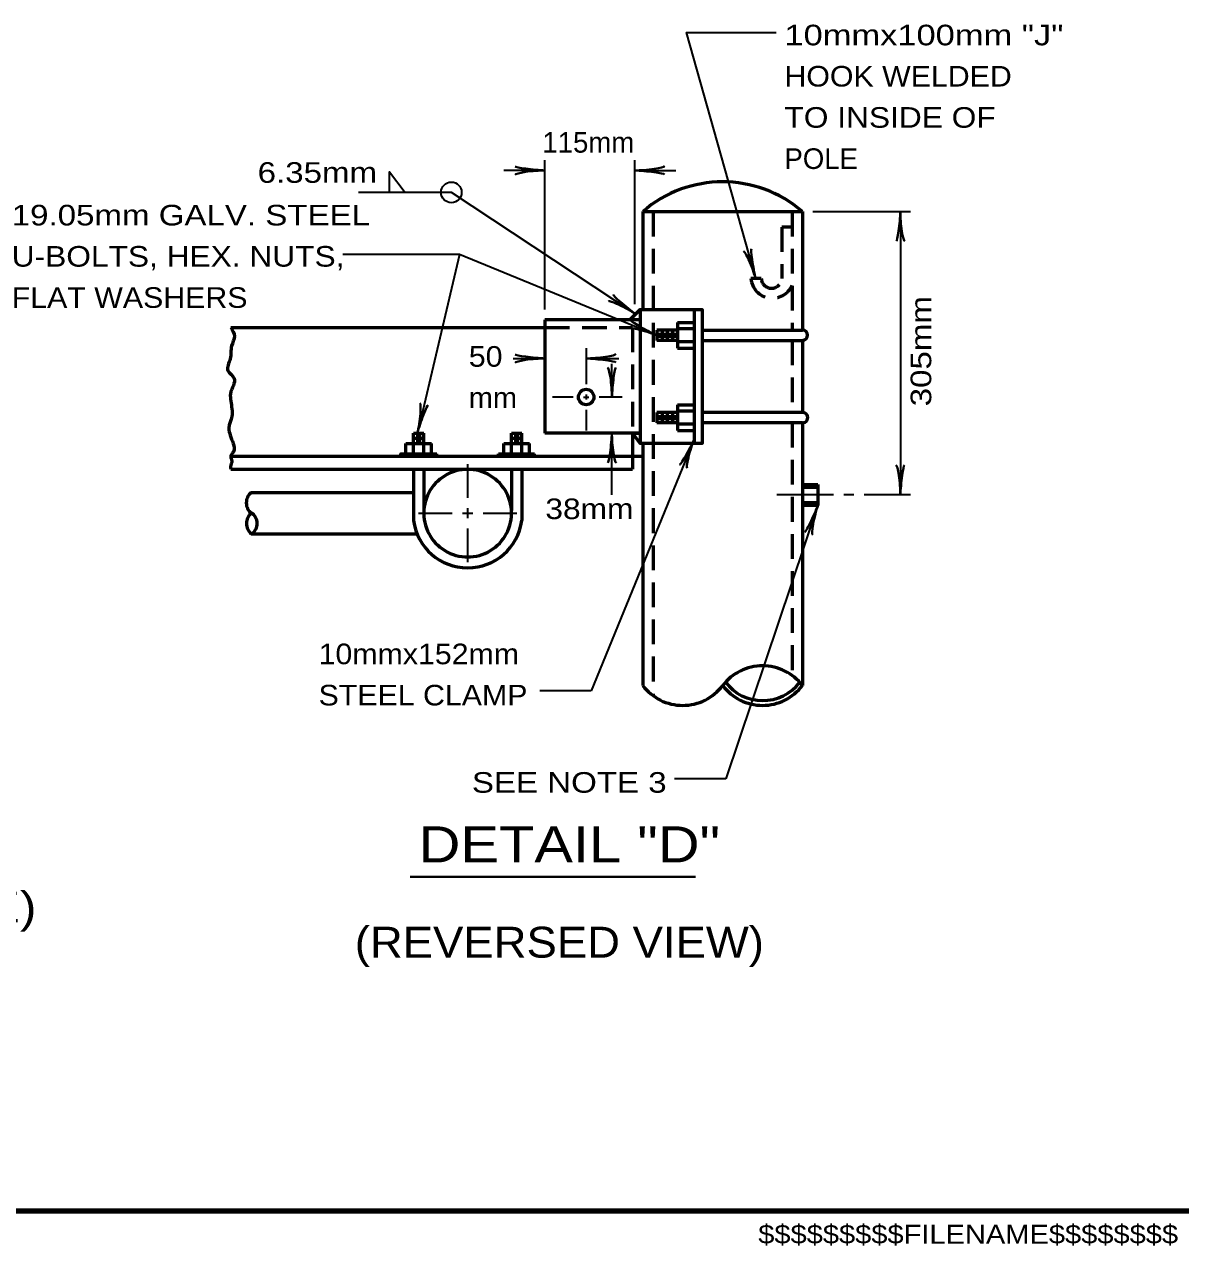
# Model space of a CAD drawing. Extents: x -35 to 821, y -13 to 531.
# Drawn here: x 455.8 to 590.5, y -5 to 137.2 of the extents above; entities that cross this region are included whole.
import ezdxf

# ---------------------------------------------------------------- set-up
doc = ezdxf.new("R2010")
doc.units = 0
doc.header["$LTSCALE"] = 0.96
doc.linetypes.add('MEDIUM_DASHED', pattern=[4.5, 3, -1.5])
doc.layers.add('1', color=7, linetype='Continuous', lineweight=53)

msp = doc.modelspace()

# ---------------------------------------------------------------- linework, layer by layer
at = {"layer": '1', "lineweight": 35}
for p, q in [((516.4637, 104.0157), (516.4637, 121.4157)), ((526.9254, 104.6349), (526.9254, 121.4157)), ((516.4637, 120.2157), (511.6637, 120.2157)), ((526.9254, 120.2157), (531.7254, 120.2157)), ((505.5655, 117.6582), (494.7655, 117.6582)), ((527.033, 103.485), (505.5655, 117.6582)), ((547.6637, 115.4157), (559.0637, 115.4157)), ((557.8637, 115.4157), (557.8637, 82.4157)), ((506.5035, 110.408), (492.9263, 110.408)), ((512.7724, 98.3157), (516.4637, 98.3157)), ((521.2637, 99.5157), (521.2637, 95.3157)), ((521.2637, 98.3157), (525.0667, 98.3157)), ((524.2637, 93.8157), (524.2637, 97.6946)), ((521.2637, 94.1157), (521.2637, 93.5157)), ((519.7637, 93.8157), (517.3637, 93.8157)), ((520.9637, 93.8157), (521.5637, 93.8157)), ((525.4637, 93.8157), (522.7637, 93.8157)), ((521.2637, 92.3157), (521.2637, 89.9157)), ((533.8637, 88.9239), (521.8519, 59.5712)), ((524.2637, 82.4157), (524.2637, 89.6157)), ((507.4637, 85.9942), (507.4637, 82.0899)), ((548.2637, 81.2157), (537.5414, 49.3356)), ((550.0637, 82.4157), (543.4637, 82.4157)), ((552.4637, 82.4157), (551.2637, 82.4157)), ((559.0637, 82.4157), (553.6637, 82.4157)), ((501.7537, 80.2899), (505.6637, 80.2899)), ((506.8637, 80.2899), (508.0637, 80.2899)), ((507.4637, 80.8899), (507.4637, 79.6899)), ((509.2637, 80.2899), (513.1737, 80.2899)), ((507.4637, 78.4899), (507.4637, 74.5856)), ((521.8519, 59.5712), (515.8519, 59.5712)), ((537.5414, 49.3356), (531.5414, 49.3356))]:
    msp.add_line(p, q, dxfattribs=at)
at = {"layer": '1'}
for p, q in [((527.8637, 115.4157), (546.4637, 115.4157)), ((527.8637, 115.4157), (527.8637, 104.0157)), ((546.4637, 115.4157), (546.4637, 101.6157)), ((527.5637, 104.0157), (526.3637, 102.8157)), ((533.8637, 104.0157), (533.8637, 88.4157)), ((516.4637, 102.8157), (516.4637, 89.6157)), ((527.5637, 102.8157), (516.4637, 102.8157)), ((531.9137, 102.5157), (531.9137, 99.5157)), ((531.9137, 102.5157), (533.8637, 102.5157)), ((479.8637, 101.9157), (516.4637, 101.9157)), ((529.5137, 101.6157), (529.5137, 100.4157)), ((531.9137, 101.6157), (529.5137, 101.6157)), ((529.8137, 101.3157), (529.8137, 100.7157)), ((530.1137, 101.6157), (530.1137, 100.4157)), ((530.4137, 101.3157), (530.4137, 100.7157)), ((530.7137, 101.6157), (530.7137, 100.4157)), ((531.0137, 101.3157), (531.0137, 100.7157)), ((531.3137, 101.6157), (531.3137, 100.4157)), ((531.6137, 101.3157), (531.6137, 100.7157)), ((533.8637, 101.7657), (531.9137, 101.7657)), ((534.7637, 101.6157), (546.4637, 101.6157)), ((531.9137, 100.4157), (529.5137, 100.4157)), ((533.8637, 100.2657), (531.9137, 100.2657)), ((534.7637, 100.4157), (546.4637, 100.4157)), ((546.4637, 100.4157), (546.4637, 92.0157)), ((531.9137, 99.5157), (533.8637, 99.5157)), ((531.9137, 92.9157), (531.9137, 89.9157)), ((531.9137, 92.9157), (533.8637, 92.9157)), ((529.5137, 92.0157), (529.5137, 90.8157)), ((531.9137, 92.0157), (529.5137, 92.0157)), ((529.8137, 91.7157), (529.8137, 91.1157)), ((530.1137, 92.0157), (530.1137, 90.8157)), ((530.4137, 91.7157), (530.4137, 91.1157)), ((530.7137, 92.0157), (530.7137, 90.8157)), ((531.0137, 91.7157), (531.0137, 91.1157)), ((531.3137, 92.0157), (531.3137, 90.8157)), ((531.6137, 91.7157), (531.6137, 91.1157)), ((533.8637, 92.1657), (531.9137, 92.1657)), ((546.4637, 92.0157), (534.7637, 92.0157)), ((531.9137, 90.8157), (529.5137, 90.8157)), ((533.8637, 90.6657), (531.9137, 90.6657)), ((531.9137, 89.9157), (533.8637, 89.9157)), ((546.4637, 90.8157), (534.7637, 90.8157)), ((546.4637, 90.8157), (546.4637, 60.2157)), ((500.2637, 87.2157), (500.2637, 88.4157)), ((500.2637, 88.4157), (503.2637, 88.4157)), ((501.1637, 87.2157), (501.1637, 89.6157)), ((501.1637, 89.6157), (502.3637, 89.6157)), ((501.1637, 89.0157), (502.3637, 89.0157)), ((501.4637, 89.3157), (502.0637, 89.3157)), ((501.4637, 88.7157), (502.0637, 88.7157)), ((502.3637, 87.2157), (502.3637, 89.6157)), ((503.2637, 87.2157), (503.2637, 88.4157)), ((511.6637, 87.2157), (511.6637, 88.4157)), ((511.6637, 88.4157), (514.6637, 88.4157)), ((512.5637, 87.2157), (512.5637, 89.6157)), ((512.5637, 89.6157), (513.7637, 89.6157)), ((512.5637, 89.0157), (513.7637, 89.0157)), ((512.8637, 89.3157), (513.4637, 89.3157)), ((512.8637, 88.7157), (513.4637, 88.7157)), ((513.7637, 87.2157), (513.7637, 89.6157)), ((514.6637, 87.2157), (514.6637, 88.4157)), ((527.5637, 89.6157), (516.4637, 89.6157)), ((526.6637, 89.6157), (526.6637, 85.4157)), ((526.6637, 89.6157), (527.5637, 88.4157)), ((527.8637, 88.4157), (527.8637, 60.2157)), ((479.8637, 86.9157), (527.8637, 86.9157)), ((503.8637, 86.9157), (503.8637, 87.2157)), ((511.0637, 86.9157), (511.0637, 87.2157)), ((511.0637, 87.2157), (515.2637, 87.2157)), ((515.2637, 86.9157), (515.2637, 87.2157)), ((501.1637, 85.4157), (501.1637, 79.4157)), ((502.3637, 85.4157), (502.3637, 80.6157)), ((512.5637, 85.4157), (512.5637, 80.6157)), ((513.7637, 85.4157), (513.7637, 79.4157)), ((482.2637, 82.6899), (501.1637, 82.6899)), ((546.4637, 83.6157), (548.2637, 83.6157)), ((548.2637, 83.6157), (548.2637, 81.2157)), ((546.4637, 81.2157), (548.2637, 81.2157)), ((482.2637, 77.8899), (501.5688, 77.8899))]:
    msp.add_line(p, q, dxfattribs=at)
at = {"layer": '1', "linetype": 'MEDIUM_DASHED'}
for p, q in [((529.0637, 115.4157), (529.0637, 59.0259)), ((545.2637, 115.4157), (545.2637, 101.6157)), ((541.6637, 107.6157), (540.4637, 107.6157)), ((545.2637, 100.4157), (545.2637, 92.0157)), ((545.2637, 90.8157), (545.2637, 61.3781)), ((546.4637, 83.3157), (548.2637, 83.3157)), ((546.4637, 81.5157), (548.2637, 81.5157))]:
    msp.add_line(p, q, dxfattribs=at)
at = {"layer": '1', "lineweight": 40}
msp.add_line((500.756, 37.9261), (533.9945, 37.9261), dxfattribs=at)
at = {"layer": '1', "lineweight": 158}
msp.add_line((814.3112, -1.0154), (22.7112, -1.0154), dxfattribs=at)
at = {"layer": '1', "lineweight": 35}
for points in [[(541.0116, 107.6157), (532.9604, 136.2721), (543.4113, 136.2721)], [(498.3655, 117.6582), (498.3655, 120.0582), (500.1655, 117.6582)], [(529.5137, 100.9955), (506.5035, 110.408), (501.6077, 89.6157)]]:
    msp.add_lwpolyline(points, dxfattribs=at)
at = {"layer": '1', "linetype": 'MEDIUM_DASHED'}
for points in [[(545.2637, 113.6157), (544.0637, 113.6157), (544.0637, 107.6157)], [(516.4637, 101.9157), (526.6637, 101.9157), (526.6637, 89.6157)]]:
    msp.add_lwpolyline(points, dxfattribs=at)
at = {"layer": '1'}
msp.add_lwpolyline([(526.3637, 102.8157), (527.5637, 104.0157), (527.5637, 102.8157)], close=True, dxfattribs=at)
for points in [[(527.5637, 104.0157), (527.5637, 88.4157), (526.6637, 89.6157), (527.5637, 89.6157), (527.5637, 88.4157)], [(527.5637, 104.0157), (534.7637, 104.0157), (534.7637, 88.4157), (527.5637, 88.4157)], [(499.6637, 86.9157), (499.6637, 87.2157), (503.8637, 87.2157)], [(479.8637, 85.4157), (502.3637, 85.4157), (512.5637, 85.4157), (526.6637, 85.4157)]]:
    msp.add_lwpolyline(points, dxfattribs=at)
at = {"layer": '1', "lineweight": 35}
msp.add_circle((505.5655, 117.6582), 1.2, dxfattribs=at)
at = {"layer": '1'}
msp.add_circle((521.2637, 93.8157), 0.9, dxfattribs=at)
for centre, radius, start, end in [((537.1637, 104.6902), 14.196, 49.07159, 130.92841), ((546.4587, 101.0157), 0.6, 270.4755, 89.5245), ((546.4753, 91.4157), 0.6001, 268.89506, 91.10493), ((507.4637, 80.2842), 5.11, 356.40861, 183.59139), ((483.1961, 81.4899), 1.5197, 127.84869, 232.15131), ((483.2529, 79.0899), 1.5552, 129.50016, 230.49985), ((481.4817, 79.0899), 1.4611, 304.78683, 56.54264), ((507.4637, 80.2956), 5.11, 176.40861, 3.59139), ((507.4637, 80.2717), 6.3579, 187.73761, 352.26239), ((541.8137, 56.6983), 5.814, 36.88966, 143.11033), ((532.5137, 63.7057), 5.814, 216.88967, 323.11034), ((541.8137, 63.7057), 5.814, 216.88967, 323.11034), ((541.8224, 63.9057), 5.4488, 217.44851, 322.41261)]:
    msp.add_arc(centre, radius, start, end, dxfattribs=at)
at = {"layer": '1', "linetype": 'MEDIUM_DASHED'}
for centre, radius, start, end in [((542.9552, 107.8269), 2.5005, 184.84499, 337.40107), ((542.8637, 107.6935), 1.2025, 183.70752, 356.29249)]:
    msp.add_arc(centre, radius, start, end, dxfattribs=at)
at = {"layer": '1', "lineweight": 40}
for centre, major_axis, ratio, start_param, end_param in [((515.1543, 119.8841), (2.1428, 0.1874), 0.122415, 0.89635335, 3.14159265), ((515.1191, 120.4696), (2.1077, -0.2108), 0.07063, 3.14071475, 5.41810995), ((528.27, 119.9618), (-2.1077, 0.2108), 0.07063, 3.14071475, 5.41810995), ((528.27, 119.9618), (-2.1077, 0.2108), 0.07063, 3.14071475, 5.41810995), ((528.2348, 120.5473), (-2.1428, -0.1874), 0.122415, 0.89635335, 3.14159265), ((528.2348, 120.5473), (-2.1428, -0.1874), 0.122415, 0.89635335, 3.14159265), ((557.6098, 114.0711), (0.2108, 2.1077), 0.07063, 3.14071475, 5.41810995), ((557.6098, 114.0711), (0.2108, 2.1077), 0.07063, 3.14071475, 5.41810995), ((558.1953, 114.1063), (-0.1874, 2.1428), 0.122415, 0.89635335, 3.14159265), ((558.1953, 114.1063), (-0.1874, 2.1428), 0.122415, 0.89635335, 3.14159265), ((540.8924, 108.9789), (-0.3672, 2.0862), 0.07063, 6.28230741, 8.55970261), ((540.3382, 108.7866), (0.76, -2.0123), 0.122415, 0.89635335, 3.14159265), ((526.0508, 104.4377), (-1.6428, 1.3372), 0.07063, 6.28230741, 8.55970261), ((525.7576, 103.9298), (1.8915, -1.0243), 0.122415, 0.89635335, 3.14159265), ((528.3653, 101.7396), (-1.871, 0.9931), 0.07063, 6.28230741, 8.55970261), ((528.1762, 101.1844), (2.0543, -0.6379), 0.122415, 0.89635335, 3.14159265), ((515.1543, 97.9841), (2.1428, 0.1874), 0.122415, 0.89635335, 3.14159265), ((515.1191, 98.5696), (2.1077, -0.2108), 0.07063, 3.14071475, 5.41810995), ((522.6083, 98.0618), (-2.1077, 0.2108), 0.07063, 3.14071475, 5.41810995), ((522.6083, 98.0618), (-2.1077, 0.2108), 0.07063, 3.14071475, 5.41810995), ((522.5731, 98.6473), (-2.1428, -0.1874), 0.122415, 0.89635335, 3.14159265), ((522.5731, 98.6473), (-2.1428, -0.1874), 0.122415, 0.89635335, 3.14159265), ((523.9321, 95.1251), (0.1874, -2.1428), 0.122415, 0.89635335, 3.14159265), ((524.5176, 95.1603), (-0.2108, -2.1077), 0.07063, 3.14071475, 5.41810995), ((501.5851, 90.9663), (-0.3087, -2.1287), 0.122415, 0.89635335, 3.14159265), ((502.163, 90.8663), (0.6883, 2.0033), 0.07063, 6.28230741, 8.55970261), ((524.0098, 88.2711), (0.2108, 2.1077), 0.07063, 3.14071475, 5.41810995), ((524.5953, 88.3063), (-0.1874, 2.1428), 0.122415, 0.89635335, 3.14159265), ((533.1194, 87.7756), (-0.9934, -1.8709), 0.07063, 6.28230741, 8.55970261), ((533.6746, 87.5864), (0.6382, 2.0542), 0.122415, 0.89635335, 3.14159265), ((557.5321, 83.7251), (0.1874, -2.1428), 0.122415, 0.89635335, 3.14159265), ((558.1176, 83.7603), (-0.2108, -2.1077), 0.07063, 3.14071475, 5.41810995), ((547.5944, 80.0222), (0.8717, 1.9306), 0.07063, 3.14071475, 5.41810995), ((548.1605, 79.8689), (0.5055, 2.0908), 0.122415, 0.89635335, 3.14159265)]:
    msp.add_ellipse(centre, major_axis=major_axis, ratio=ratio, start_param=start_param, end_param=end_param, dxfattribs=at)
at = {"layer": '1'}
msp.add_spline([(479.8637, 101.9157), (480.2966, 100.9041), (479.9599, 99.7714), (479.8069, 98.2713), (479.5315, 96.8937), (480.266, 95.9753), (480.1742, 95.1793), (479.8375, 94.1997), (479.8681, 93.3425), (479.9905, 91.5669), (479.6539, 90.1893), (479.8069, 89.3627), (480.1435, 88.4137), (480.1742, 87.434), (479.8637, 86.9157), (479.9905, 86.3625), (479.8375, 85.7196), (479.8637, 85.4157)], degree=3, dxfattribs=at)

# ---------------------------------------------------------------- texts
for s, height, width, p in [('10mmx100mm "J"', 2.4, 1.25, (544.3629, 134.7911)), ('HOOK WELDED', 2.4, 1.1, (544.3629, 129.9911)), ('TO INSIDE OF', 2.4, 1.15, (544.3629, 125.1911)), ('6.35mm', 2.4, 1.2, (482.9998, 118.7749)), ('19.05mm GALV. STEEL', 2.4, 1.2, (454.356, 113.8082)), ('U-BOLTS, HEX. NUTS,', 2.4, 1.15, (454.356, 109.0082)), ('FLAT WASHERS', 2.4, 1.1, (454.356, 104.2082)), ('50', 2.4, 1.1, (507.5988, 97.3489)), ('mm', 2.4, 1.05, (507.5988, 92.5489)), ('38mm', 2.4, 1.15, (516.515, 79.5962)), ('10mmx152mm', 2.4, 1.1, (490.1014, 62.6888)), ('STEEL CLAMP', 2.4, 1.1, (490.1014, 57.8888)), ('SEE NOTE 3', 2.4, 1.2, (507.9569, 47.7191)), ('DETAIL "D"', 4.2, 1.2, (501.7508, 39.6045)), ('(DETAIL "D" ALTERNATE)', 3.6, 1.2, (387.6569, 32.6056)), ('(REVERSED VIEW)', 3.6, 1.1, (494.3123, 28.5055)), ('$$$$$$$$$FILENAME$$$$$$$$', 2.2, 1.15, (541.3112, -4.8154))]:
    msp.add_text(s, height=height, dxfattribs=dict(at, width=width)).set_placement(p)
for s, p in [('115mm', (516.168, 122.291)), ('POLE', (544.3629, 120.3911))]:
    msp.add_text(s, height=2.4, dxfattribs=at).set_placement(p)
at = {"layer": '1', "width": 1.2}
msp.add_text('305mm', height=2.4, rotation=90, dxfattribs=at).set_placement((561.4632, 92.7359))

doc.saveas('drawing.dxf')
